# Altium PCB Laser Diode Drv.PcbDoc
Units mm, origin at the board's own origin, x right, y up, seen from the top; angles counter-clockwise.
Board outline 152.4 x 101.6 mm, 2 copper layers (Top Layer, Bottom Layer); 8 components, 0 nets, 31 pads, 0 vias.
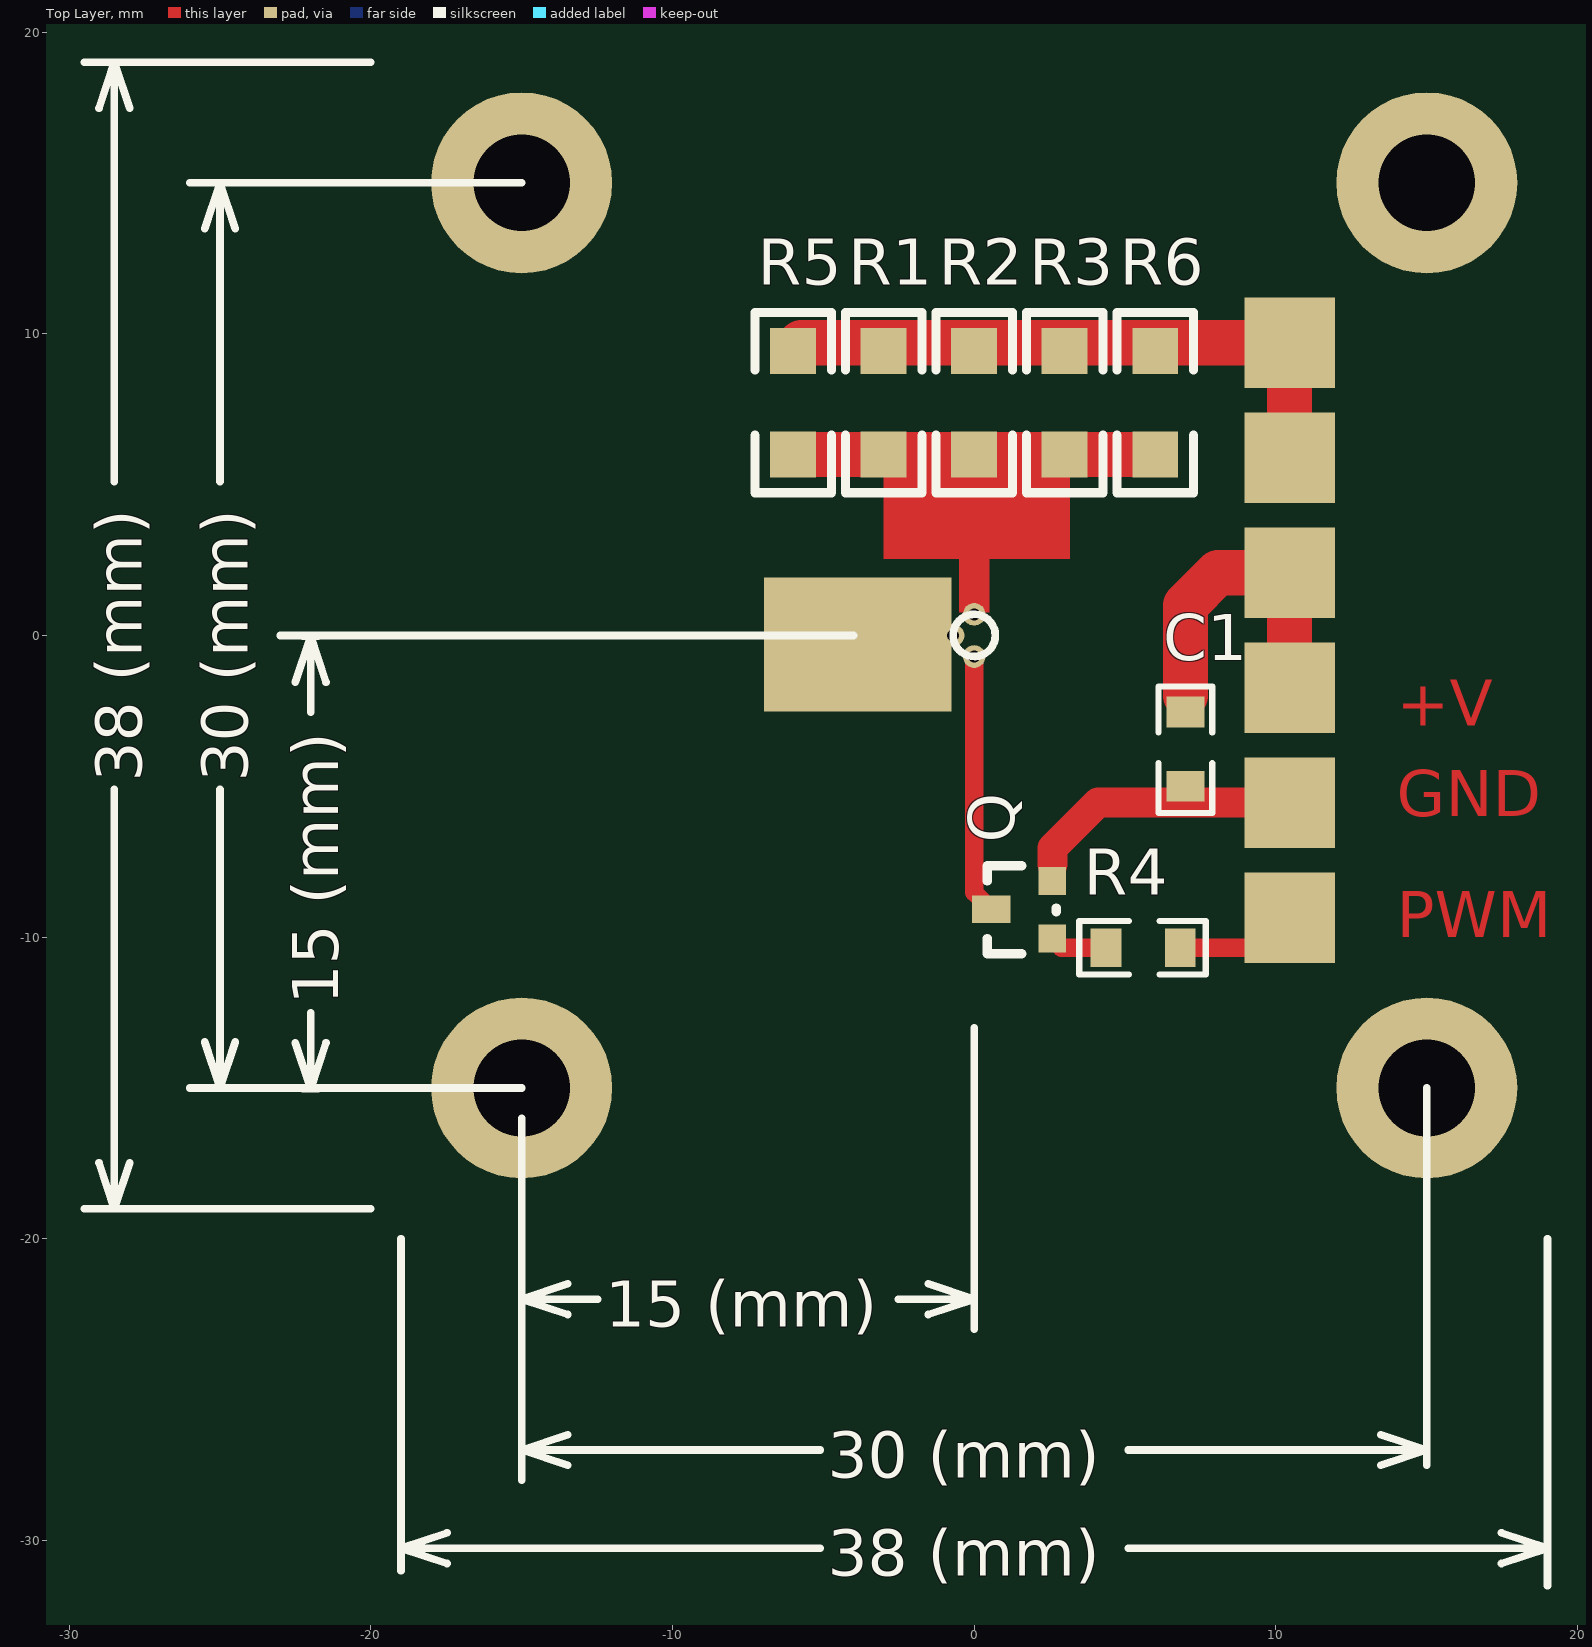
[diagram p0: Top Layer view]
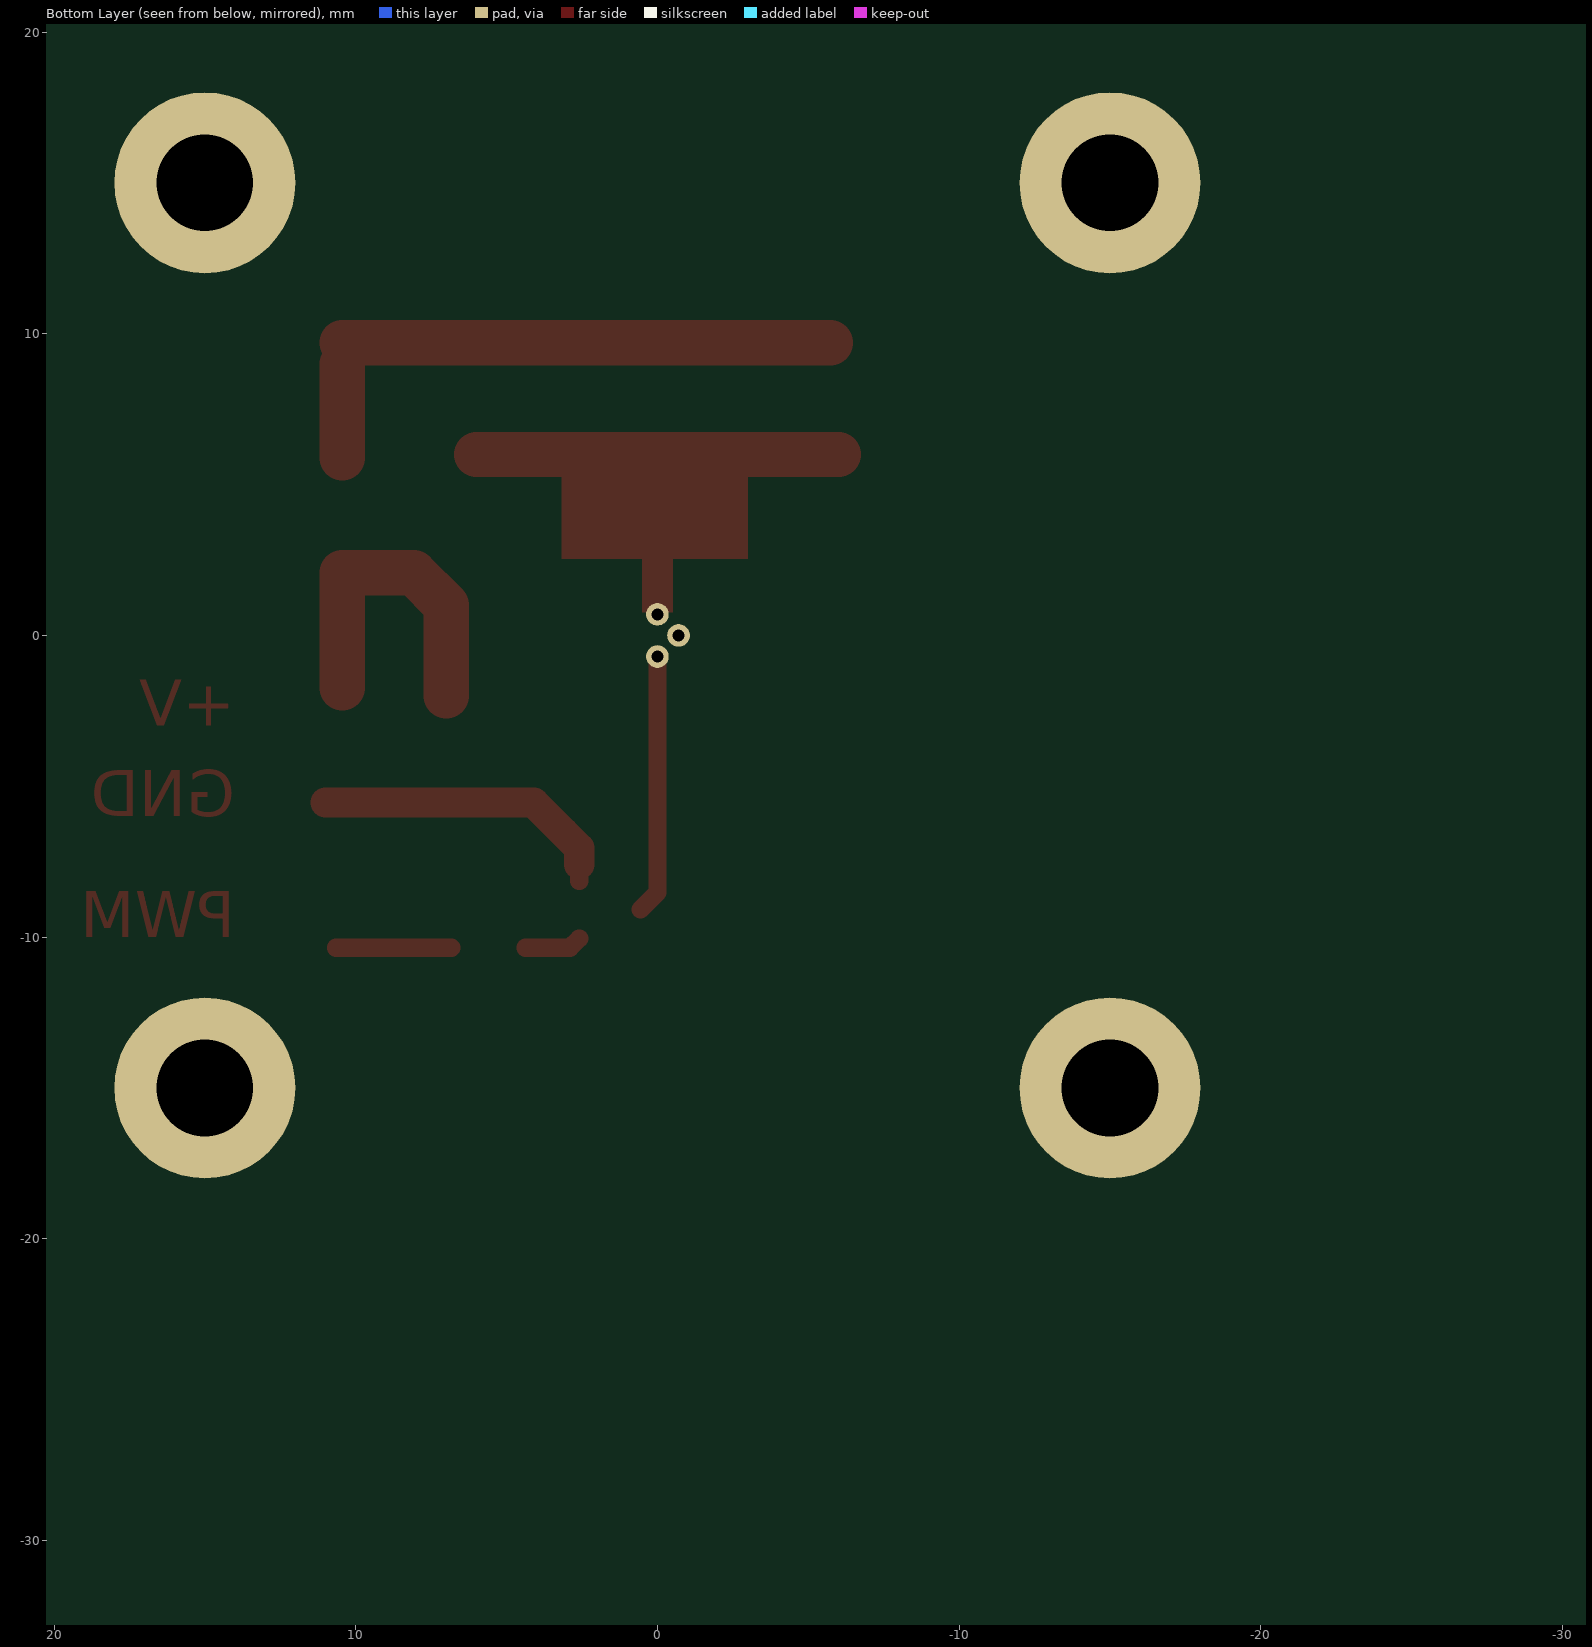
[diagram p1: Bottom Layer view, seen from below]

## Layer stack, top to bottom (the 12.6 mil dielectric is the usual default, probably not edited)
Top Solder: solder mask 0.0102, Solder Resist, Dk 3.5
Top Layer: signal copper 0.0356
Dielectric 1: dielectric 0.32, FR-4, Dk 4.8
Bottom Layer: signal copper 0.0356
Bottom Solder: solder mask 0.0102, Solder Resist, Dk 3.5

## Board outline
-43.851,-35.626 108.549,-35.626 108.549,65.974 -43.851,65.974

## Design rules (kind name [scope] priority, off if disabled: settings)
Clearance [All] p1: gap=0.254 ignorepadtopadclearanceinfootprint=FALSE except(0: Arc-Hole Track-Hole SMDPad-Hole THPad-Hole Via-Hole Fill-Hole Poly-Hole Region-Hole Text-Hole)
PolygonConnect [All] p1: connectstyle=Relief reliefconductorwidth=0.254 reliefentries=4 polygonreliefangle="90 Angle" airgapwidth=0.254
RoutingVias [All] p1: holewidth=0.711 width=1.27 viastyle="Through Hole" minholewidth=0.711 minwidth=1.27 maxholewidth=0.711 maxwidth=1.27
SolderMaskExpansion [All] p1: expansion=0.102
Width [All] p1: maxlimit=10 minlimit=0.254 preferedwidth=0.254 minimp=50.000000 maximp=50.000000 favimp=50.000000
30 further rules are at their usual default settings.

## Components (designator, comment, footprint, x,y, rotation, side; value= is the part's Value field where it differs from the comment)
C1 "" 0805 7,-5 r90 top
Q "" SOT-23 2.592,-10.045 r90 top
R1 "" 1206 -3,9.429 r270 top
R2 "" 1206 0,9.429 r270 top
R3 "" 1206 3,9.429 r270 top
R4 "" 0805 4.37,-10.35 r0 top
R5 "" 1206 -6,9.429 r270 top
R6 "" 1206 6,9.429 r270 top

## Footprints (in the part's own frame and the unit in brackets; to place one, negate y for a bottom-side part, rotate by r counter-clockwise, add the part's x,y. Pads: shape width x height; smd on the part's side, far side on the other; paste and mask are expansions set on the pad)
0805 [mil]
  rect 40x50 smd: 1(0,0) 2(97,0)
  silkscreen extent -35,-35 130,35
1206 [mil]
  rect 60x60 smd: 1(0,0) 2(135,0)
  silkscreen extent -50,-50 185,50
SOT-23 [mil]
  rect 36x50 smd: D(38,80)
  rect 36x36 smd: G(0,0) S(75,0)
  silkscreen extent -20,-5 95,85

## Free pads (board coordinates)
  rect 3x3 smd: 1(10.45,-1.73) 1(10.45,9.7) 3(10.45,-5.54) 3(10.45,5.89) 4(10.45,-9.35) 4(10.45,2.08)
  round 6 hole 3.2: 5(-15,15) 6(15,15) 7(-15,-15) 8(15,-15)
  round 0.75 hole 0.4: A(0,0.7) CASE(-0.7,0) K(0,-0.7)
  rect 6.223x4.445 smd mask+0.05: ""(-3.861,-0.305)

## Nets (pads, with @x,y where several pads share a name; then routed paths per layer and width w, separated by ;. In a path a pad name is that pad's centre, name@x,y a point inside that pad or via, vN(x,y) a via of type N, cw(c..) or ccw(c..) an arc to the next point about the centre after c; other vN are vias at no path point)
pads on no net: C1.1 C1.2 Q.D Q.G Q.S R1.1 R1.2 R2.1 R2.2 R3.1 R3.2 R4.1 R4.2 R5.1 R5.2 R6.1 R6.2
copper on no net: | length 76.8
  Top Layer w0.6: -2.695,9.525 4.925,9.525 ; 0,-0.7 0,-8.52 0.56,-9.08 ; 2.592,-10.045 2.897,-10.35 4.37,-10.35 ; 2.592,-8.14 2.592,-7.048 3.1,-6.54 ; 6.834,-10.35 9.45,-10.35 10.65,-10.35
  Top Layer w1: 2.592,-7.594 2.592,-7.048 4.1,-5.54 ; 3.1,-6.54 4.1,-5.54 ; 11,-5.54 4.1,-5.54
  Top Layer w1.5: -6,6 6,6 ; -5.729,9.7 10.45,9.7 ; 7,-2 7,1 8.08,2.08 10.45,2.08 10.45,-1.73 ; 10.45,5.89 10.45,9

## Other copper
Top Layer:
  rectangle: -3,2.54 3.175,6
  rectangle: -0.508,0.762 0.508,6
  text "+V" at 14,-3 h1.52
  text "GND" at 14,-6 h1.52
  text "PWM" at 14,-10 h1.52

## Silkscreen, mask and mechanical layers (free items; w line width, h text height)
Top Overlay:
  circle w0.254: c0,0 r0.7
  lines w0.254: -29.5,-19 -20,-19 ; -29.5,19 -20,19 ; -29.008,-17.476 -28.5,-19 ; -29.008,17.476 -28.5,19 ; -28.754,-19 -28.246,-19 ; -28.754,19 -28.246,19 ; -28.5,-5.104 -28.5,-19 ; -28.5,5.104 -28.5,19 ; -27.992,-17.476 -28.5,-19 ; -27.992,17.476 -28.5,19 ; -26,-15 -15,-15 ; -26,15 -15,15 ; -25.508,-13.476 -25,-15 ; -25.508,13.476 -25,15 ; -25.254,-15 -24.746,-15 ; -25.254,15 -24.746,15 ; -25,-5.104 -25,-15 ; -25,5.104 -25,15 ; -24.492,-13.476 -25,-15 ; -24.492,13.476 -25,15 ; -23,0 -4,0 ; -22.5,-13.5 -21.992,-15.024 ; -22.5,-1.548 -21.992,-0.024 ; -22.246,-15.024 -21.738,-15.024 ; -22.246,-0.024 -21.738,-0.024 ; -21.992,-12.501 -21.992,-15.024 ; -21.992,-2.547 -21.992,-0.024 ; -21.484,-13.5 -21.992,-15.024 ; -21.484,-1.548 -21.992,-0.024 ; -19,-31 -19,-20 ; -19,-30.508 -19,-30 ; -17.476,-30.762 -19,-30.254 ; -17.476,-29.746 -19,-30.254 ; -15,-28 -15,-16 ; -15,-27.254 -15,-26.746 ; -15,-22.254 -15,-21.746 ; -13.476,-27.508 -15,-27 ; -13.476,-26.492 -15,-27 ; -13.476,-22.508 -15,-22 ; -13.476,-21.492 -15,-22 ; -12.477,-22 -15,-22 ; -5.104,-30.254 -19,-30.254 ; -5.104,-27 -15,-27 ; -2.523,-22 0,-22 ; -1.524,-22.508 0,-22 ; -1.524,-21.492 0,-22 ; 0,-23 0,-13 ; 0,-22.254 0,-21.746 ; 5.104,-30.254 19,-30.254 ; 5.104,-27 15,-27 ; 13.476,-27.508 15,-27 ; 13.476,-26.492 15,-27 ; 15,-27.5 15,-15 ; 15,-27.254 15,-26.746 ; 17.476,-30.762 19,-30.254 ; 17.476,-29.746 19,-30.254 ; 19,-31.5 19,-20 ; 19,-30.508 19,-30
  text "38 (mm)" at -27.586,-4.85 h1.52 r90
  text "30 (mm)" at -24.086,-4.85 h1.52 r90
  text "15 (mm)" at -21.078,-12.247 h1.52 r90
  text "15 (mm)" at -12.223,-22.914 h1.52
  text "30 (mm)" at -4.85,-27.914 h1.52
  text "38 (mm)" at -4.85,-31.168 h1.52
Mechanical 1:
  lines w0.254: -19,-19 -19,19 19,19 19,-19 3,-19 -19,-19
